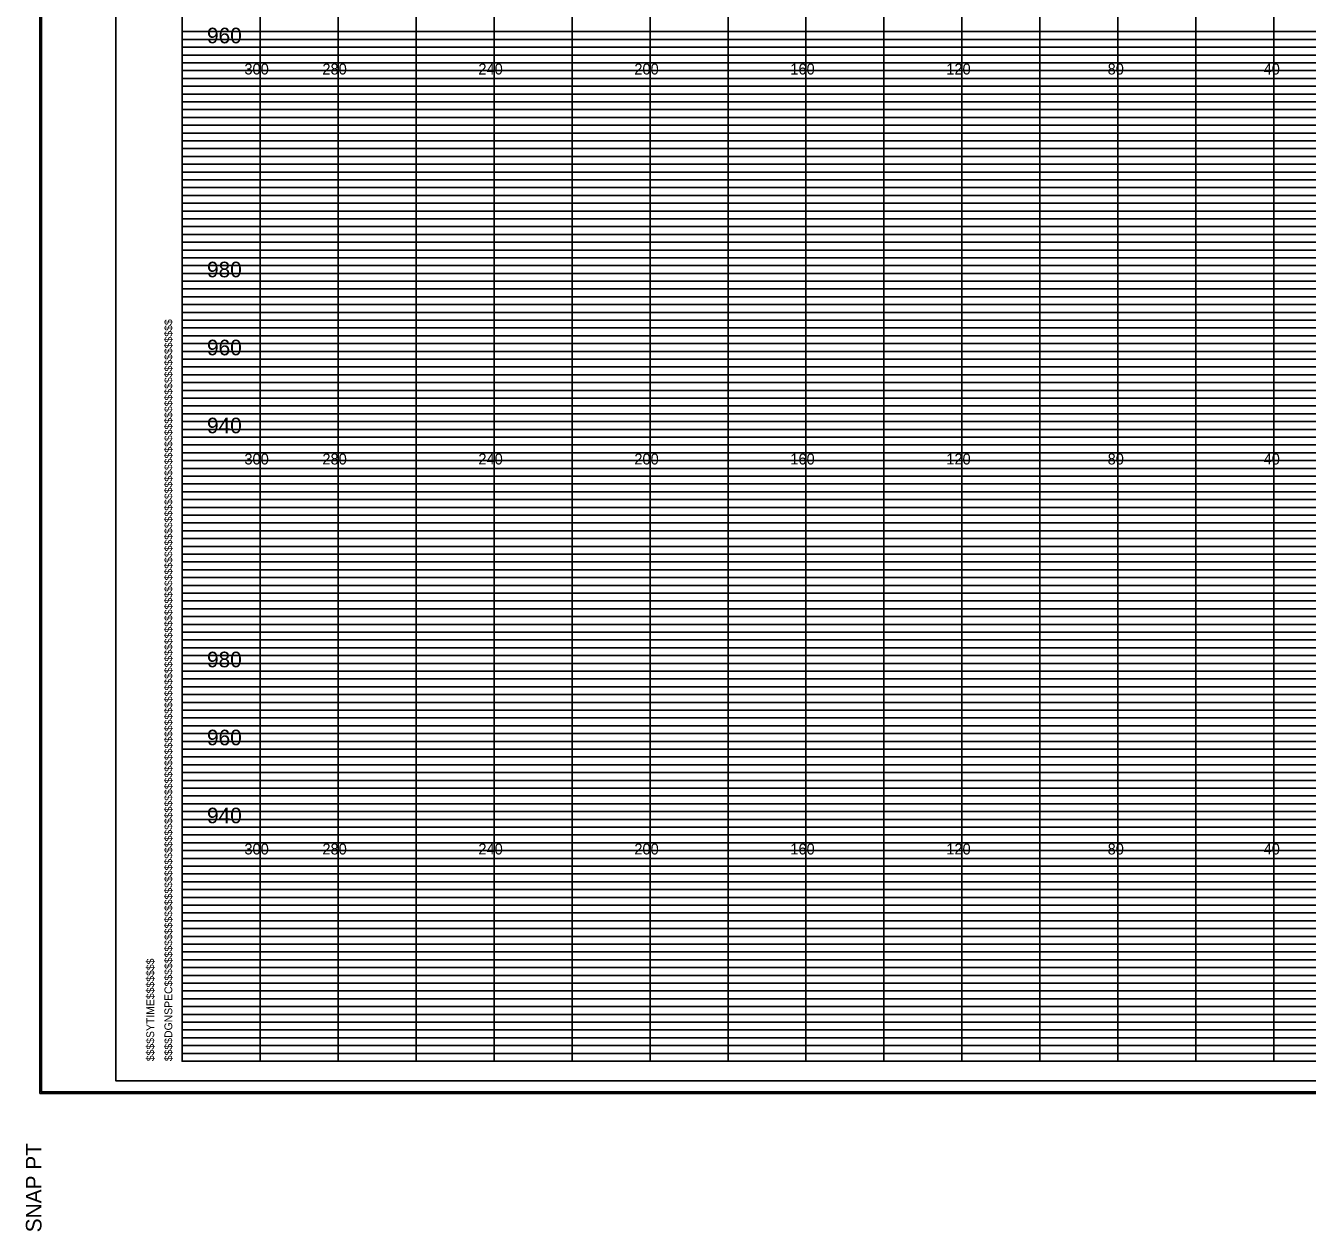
# Model space of a CAD drawing. Extents: x 2313580 to 2322968, y 282099 to 303247.
# Drawn here: x 2320006 to 2320334.7, y 287544 to 287853.2 of the extents above; entities that cross this region are included whole.
import ezdxf

# ---------------------------------------------------------------- set-up
doc = ezdxf.new("R2010")
doc.units = 0
for name, color, linetype in [('DESIGN - SHEET - Corner Text', 7, 'Continuous'), ('DESIGN - SHEET - Light Grid', 7, 'Continuous'), ('DESIGN - SHEET - Linework', 7, 'Continuous'), ('DESIGN - SHEET - Plot Shape', 7, 'Continuous'), ('DESIGN - TYPICAL - Text', 7, 'Continuous')]:
    doc.layers.add(name, color=color, linetype=linetype)

msp = doc.modelspace()

# ---------------------------------------------------------------- linework, layer by layer
at = {"layer": 'DESIGN - SHEET - Light Grid'}
for p, q in [((2320046.08, 287851.67), (2320206.08, 287851.67)), ((2320046.08, 287849.67), (2320206.08, 287849.67)), ((2320206.08, 287851.67), (2320366.08, 287851.67)), ((2320206.08, 287849.67), (2320366.08, 287849.67)), ((2320046.08, 287845.67), (2320206.08, 287845.67)), ((2320206.08, 287845.67), (2320366.08, 287845.67)), ((2320046.08, 287843.67), (2320206.08, 287843.67)), ((2320206.08, 287843.67), (2320366.08, 287843.67)), ((2320046.08, 287841.67), (2320206.08, 287841.67)), ((2320046.08, 287839.67), (2320206.08, 287839.67)), ((2320206.08, 287841.67), (2320366.08, 287841.67)), ((2320206.08, 287839.67), (2320366.08, 287839.67)), ((2320046.08, 287837.67), (2320206.08, 287837.67)), ((2320046.08, 287835.67), (2320206.08, 287835.67)), ((2320206.08, 287837.67), (2320366.08, 287837.67)), ((2320206.08, 287835.67), (2320366.08, 287835.67)), ((2320046.08, 287833.67), (2320206.08, 287833.67)), ((2320206.08, 287833.67), (2320366.08, 287833.67)), ((2320046.08, 287831.67), (2320206.08, 287831.67)), ((2320046.08, 287829.67), (2320206.08, 287829.67)), ((2320206.08, 287831.67), (2320366.08, 287831.67)), ((2320206.08, 287829.67), (2320366.08, 287829.67)), ((2320046.08, 287825.67), (2320206.08, 287825.67)), ((2320206.08, 287825.67), (2320366.08, 287825.67)), ((2320046.08, 287823.67), (2320206.08, 287823.67)), ((2320206.08, 287823.67), (2320366.08, 287823.67)), ((2320046.08, 287821.67), (2320206.08, 287821.67)), ((2320046.08, 287819.67), (2320206.08, 287819.67)), ((2320206.08, 287821.67), (2320366.08, 287821.67)), ((2320206.08, 287819.67), (2320366.08, 287819.67)), ((2320046.08, 287817.67), (2320206.08, 287817.67)), ((2320206.08, 287817.67), (2320366.08, 287817.67)), ((2320046.08, 287815.67), (2320206.08, 287815.67)), ((2320046.08, 287813.67), (2320206.08, 287813.67)), ((2320206.08, 287815.67), (2320366.08, 287815.67)), ((2320206.08, 287813.67), (2320366.08, 287813.67)), ((2320046.08, 287811.67), (2320206.08, 287811.67)), ((2320046.08, 287809.67), (2320206.08, 287809.67)), ((2320206.08, 287811.67), (2320366.08, 287811.67)), ((2320206.08, 287809.67), (2320366.08, 287809.67)), ((2320046.08, 287805.67), (2320206.08, 287805.67)), ((2320046.08, 287803.67), (2320206.08, 287803.67)), ((2320206.08, 287805.67), (2320366.08, 287805.67)), ((2320206.08, 287803.67), (2320366.08, 287803.67)), ((2320046.08, 287801.67), (2320206.08, 287801.67)), ((2320046.08, 287799.67), (2320206.08, 287799.67)), ((2320206.08, 287801.67), (2320366.08, 287801.67)), ((2320206.08, 287799.67), (2320366.08, 287799.67)), ((2320046.08, 287797.67), (2320206.08, 287797.67)), ((2320206.08, 287797.67), (2320366.08, 287797.67)), ((2320046.08, 287795.67), (2320206.08, 287795.67)), ((2320046.08, 287793.67), (2320206.08, 287793.67)), ((2320206.08, 287795.67), (2320366.08, 287795.67)), ((2320206.08, 287793.67), (2320366.08, 287793.67)), ((2320046.08, 287791.67), (2320206.08, 287791.67)), ((2320046.08, 287789.67), (2320206.08, 287789.67)), ((2320206.08, 287791.67), (2320366.08, 287791.67)), ((2320206.08, 287789.67), (2320366.08, 287789.67)), ((2320046.08, 287785.67), (2320206.08, 287785.67)), ((2320046.08, 287783.67), (2320206.08, 287783.67)), ((2320206.08, 287785.67), (2320366.08, 287785.67)), ((2320206.08, 287783.67), (2320366.08, 287783.67)), ((2320046.08, 287781.67), (2320206.08, 287781.67)), ((2320046.08, 287779.67), (2320206.08, 287779.67)), ((2320206.08, 287781.67), (2320366.08, 287781.67)), ((2320206.08, 287779.67), (2320366.08, 287779.67)), ((2320046.08, 287777.67), (2320206.08, 287777.67)), ((2320206.08, 287777.67), (2320366.08, 287777.67)), ((2320046.08, 287775.67), (2320206.08, 287775.67)), ((2320046.08, 287773.67), (2320206.08, 287773.67)), ((2320206.08, 287775.67), (2320366.08, 287775.67)), ((2320206.08, 287773.67), (2320366.08, 287773.67)), ((2320046.08, 287771.67), (2320206.08, 287771.67)), ((2320206.08, 287771.67), (2320366.08, 287771.67)), ((2320046.08, 287769.67), (2320206.08, 287769.67)), ((2320206.08, 287769.67), (2320366.08, 287769.67)), ((2320046.08, 287765.67), (2320206.08, 287765.67)), ((2320046.08, 287763.67), (2320206.08, 287763.67)), ((2320206.08, 287765.67), (2320366.08, 287765.67)), ((2320206.08, 287763.67), (2320366.08, 287763.67)), ((2320046.08, 287761.67), (2320206.08, 287761.67)), ((2320206.08, 287761.67), (2320366.08, 287761.67)), ((2320046.08, 287759.67), (2320206.08, 287759.67)), ((2320046.08, 287757.67), (2320206.08, 287757.67)), ((2320206.08, 287759.67), (2320366.08, 287759.67)), ((2320206.08, 287757.67), (2320366.08, 287757.67)), ((2320046.08, 287755.67), (2320206.08, 287755.67)), ((2320046.08, 287753.67), (2320206.08, 287753.67)), ((2320206.08, 287755.67), (2320366.08, 287755.67)), ((2320206.08, 287753.67), (2320366.08, 287753.67)), ((2320046.08, 287751.67), (2320206.08, 287751.67)), ((2320206.08, 287751.67), (2320366.08, 287751.67)), ((2320046.08, 287749.67), (2320206.08, 287749.67)), ((2320206.08, 287749.67), (2320366.08, 287749.67)), ((2320046.08, 287745.67), (2320206.08, 287745.67)), ((2320046.08, 287743.67), (2320206.08, 287743.67)), ((2320206.08, 287745.67), (2320366.08, 287745.67)), ((2320206.08, 287743.67), (2320366.08, 287743.67)), ((2320046.08, 287741.67), (2320206.08, 287741.67)), ((2320206.08, 287741.67), (2320366.08, 287741.67)), ((2320046.08, 287739.67), (2320206.08, 287739.67)), ((2320046.08, 287737.67), (2320206.08, 287737.67)), ((2320206.08, 287739.67), (2320366.08, 287739.67)), ((2320206.08, 287737.67), (2320366.08, 287737.67)), ((2320046.08, 287735.67), (2320206.08, 287735.67)), ((2320046.08, 287733.67), (2320206.08, 287733.67)), ((2320206.08, 287735.67), (2320366.08, 287735.67)), ((2320206.08, 287733.67), (2320366.08, 287733.67)), ((2320046.08, 287731.67), (2320206.08, 287731.67)), ((2320206.08, 287731.67), (2320366.08, 287731.67)), ((2320046.08, 287729.67), (2320206.08, 287729.67)), ((2320206.08, 287729.67), (2320366.08, 287729.67)), ((2320046.08, 287725.67), (2320206.08, 287725.67)), ((2320206.08, 287725.67), (2320366.08, 287725.67)), ((2320046.08, 287723.67), (2320206.08, 287723.67)), ((2320046.08, 287721.67), (2320206.08, 287721.67)), ((2320206.08, 287723.67), (2320366.08, 287723.67)), ((2320206.08, 287721.67), (2320366.08, 287721.67)), ((2320046.08, 287719.67), (2320206.08, 287719.67)), ((2320046.08, 287717.67), (2320206.08, 287717.67)), ((2320206.08, 287719.67), (2320366.08, 287719.67)), ((2320206.08, 287717.67), (2320366.08, 287717.67)), ((2320046.08, 287715.67), (2320206.08, 287715.67)), ((2320206.08, 287715.67), (2320366.08, 287715.67)), ((2320046.08, 287713.67), (2320206.08, 287713.67)), ((2320046.08, 287711.67), (2320206.08, 287711.67)), ((2320206.08, 287713.67), (2320366.08, 287713.67)), ((2320206.08, 287711.67), (2320366.08, 287711.67)), ((2320046.08, 287709.67), (2320206.08, 287709.67)), ((2320206.08, 287709.67), (2320366.08, 287709.67)), ((2320046.08, 287705.67), (2320206.08, 287705.67)), ((2320206.08, 287705.67), (2320366.08, 287705.67)), ((2320046.08, 287703.67), (2320206.08, 287703.67)), ((2320046.08, 287701.67), (2320206.08, 287701.67)), ((2320206.08, 287703.67), (2320366.08, 287703.67)), ((2320206.08, 287701.67), (2320366.08, 287701.67)), ((2320046.08, 287699.67), (2320206.08, 287699.67)), ((2320046.08, 287697.67), (2320206.08, 287697.67)), ((2320206.08, 287699.67), (2320366.08, 287699.67)), ((2320206.08, 287697.67), (2320366.08, 287697.67)), ((2320046.08, 287695.67), (2320206.08, 287695.67)), ((2320206.08, 287695.67), (2320366.08, 287695.67)), ((2320046.08, 287693.67), (2320206.08, 287693.67)), ((2320046.08, 287691.67), (2320206.08, 287691.67)), ((2320206.08, 287693.67), (2320366.08, 287693.67)), ((2320206.08, 287691.67), (2320366.08, 287691.67)), ((2320046.08, 287689.67), (2320206.08, 287689.67)), ((2320206.08, 287689.67), (2320366.08, 287689.67)), ((2320046.08, 287685.67), (2320206.08, 287685.67)), ((2320206.08, 287685.67), (2320366.08, 287685.67)), ((2320046.08, 287683.67), (2320206.08, 287683.67)), ((2320046.08, 287681.67), (2320206.08, 287681.67)), ((2320206.08, 287683.67), (2320366.08, 287683.67)), ((2320206.08, 287681.67), (2320366.08, 287681.67)), ((2320046.08, 287679.67), (2320206.08, 287679.67)), ((2320046.08, 287677.67), (2320206.08, 287677.67)), ((2320206.08, 287679.67), (2320366.08, 287679.67)), ((2320206.08, 287677.67), (2320366.08, 287677.67)), ((2320046.08, 287675.67), (2320206.08, 287675.67)), ((2320206.08, 287675.67), (2320366.08, 287675.67)), ((2320046.08, 287673.67), (2320206.08, 287673.67)), ((2320046.08, 287671.67), (2320206.08, 287671.67)), ((2320206.08, 287673.67), (2320366.08, 287673.67)), ((2320206.08, 287671.67), (2320366.08, 287671.67)), ((2320046.08, 287669.67), (2320206.08, 287669.67)), ((2320206.08, 287669.67), (2320366.08, 287669.67)), ((2320046.08, 287665.67), (2320206.08, 287665.67)), ((2320206.08, 287665.67), (2320366.08, 287665.67)), ((2320046.08, 287663.67), (2320206.08, 287663.67)), ((2320046.08, 287661.67), (2320206.08, 287661.67)), ((2320206.08, 287663.67), (2320366.08, 287663.67)), ((2320206.08, 287661.67), (2320366.08, 287661.67)), ((2320046.08, 287659.67), (2320206.08, 287659.67)), ((2320206.08, 287659.67), (2320366.08, 287659.67)), ((2320046.08, 287657.67), (2320206.08, 287657.67)), ((2320046.08, 287655.67), (2320206.08, 287655.67)), ((2320206.08, 287657.67), (2320366.08, 287657.67)), ((2320206.08, 287655.67), (2320366.08, 287655.67)), ((2320046.08, 287653.67), (2320206.08, 287653.67)), ((2320046.08, 287651.67), (2320206.08, 287651.67)), ((2320206.08, 287653.67), (2320366.08, 287653.67)), ((2320206.08, 287651.67), (2320366.08, 287651.67)), ((2320046.08, 287649.67), (2320206.08, 287649.67)), ((2320206.08, 287649.67), (2320366.08, 287649.67)), ((2320046.08, 287645.67), (2320206.08, 287645.67)), ((2320206.08, 287645.67), (2320366.08, 287645.67)), ((2320046.08, 287643.67), (2320206.08, 287643.67)), ((2320046.08, 287641.67), (2320206.08, 287641.67)), ((2320206.08, 287643.67), (2320366.08, 287643.67)), ((2320206.08, 287641.67), (2320366.08, 287641.67)), ((2320046.08, 287639.67), (2320206.08, 287639.67)), ((2320206.08, 287639.67), (2320366.08, 287639.67)), ((2320046.08, 287637.67), (2320206.08, 287637.67)), ((2320046.08, 287635.67), (2320206.08, 287635.67)), ((2320206.08, 287637.67), (2320366.08, 287637.67)), ((2320206.08, 287635.67), (2320366.08, 287635.67)), ((2320046.08, 287633.67), (2320206.08, 287633.67)), ((2320046.08, 287631.67), (2320206.08, 287631.67)), ((2320206.08, 287633.67), (2320366.08, 287633.67)), ((2320206.08, 287631.67), (2320366.08, 287631.67)), ((2320046.08, 287629.67), (2320206.08, 287629.67)), ((2320206.08, 287629.67), (2320366.08, 287629.67)), ((2320046.08, 287625.67), (2320206.08, 287625.67)), ((2320206.08, 287625.67), (2320366.08, 287625.67)), ((2320046.08, 287623.67), (2320206.08, 287623.67)), ((2320206.08, 287623.67), (2320366.08, 287623.67)), ((2320046.08, 287621.67), (2320206.08, 287621.67)), ((2320046.08, 287619.67), (2320206.08, 287619.67)), ((2320206.08, 287621.67), (2320366.08, 287621.67)), ((2320206.08, 287619.67), (2320366.08, 287619.67)), ((2320046.08, 287617.67), (2320206.08, 287617.67)), ((2320046.08, 287615.67), (2320206.08, 287615.67)), ((2320206.08, 287617.67), (2320366.08, 287617.67)), ((2320206.08, 287615.67), (2320366.08, 287615.67)), ((2320046.08, 287613.67), (2320206.08, 287613.67)), ((2320206.08, 287613.67), (2320366.08, 287613.67)), ((2320046.08, 287611.67), (2320206.08, 287611.67)), ((2320046.08, 287609.67), (2320206.08, 287609.67)), ((2320206.08, 287611.67), (2320366.08, 287611.67)), ((2320206.08, 287609.67), (2320366.08, 287609.67)), ((2320046.08, 287605.67), (2320206.08, 287605.67)), ((2320206.08, 287605.67), (2320366.08, 287605.67)), ((2320046.08, 287603.67), (2320206.08, 287603.67)), ((2320206.08, 287603.67), (2320366.08, 287603.67)), ((2320046.08, 287601.67), (2320206.08, 287601.67)), ((2320046.08, 287599.67), (2320206.08, 287599.67)), ((2320206.08, 287601.67), (2320366.08, 287601.67)), ((2320206.08, 287599.67), (2320366.08, 287599.67)), ((2320046.08, 287597.67), (2320206.08, 287597.67)), ((2320046.08, 287595.67), (2320206.08, 287595.67)), ((2320206.08, 287597.67), (2320366.08, 287597.67)), ((2320206.08, 287595.67), (2320366.08, 287595.67)), ((2320046.08, 287593.67), (2320206.08, 287593.67)), ((2320206.08, 287593.67), (2320366.08, 287593.67)), ((2320046.08, 287591.67), (2320206.08, 287591.67)), ((2320046.08, 287589.67), (2320206.08, 287589.67)), ((2320206.08, 287591.67), (2320366.08, 287591.67)), ((2320206.08, 287589.67), (2320366.08, 287589.67))]:
    msp.add_line(p, q, dxfattribs=at)
at = {"layer": 'DESIGN - SHEET - Linework'}
for p, q in [((2320009.62, 287579.39), (2320009.62, 288015.95)), ((2320066.08, 287587.67), (2320066.08, 288007.67)), ((2320086.08, 287587.67), (2320086.08, 288007.67)), ((2320106.08, 287587.67), (2320106.08, 288007.67)), ((2320126.08, 287587.67), (2320126.08, 288007.67)), ((2320146.08, 287587.67), (2320146.08, 288007.67)), ((2320166.08, 287587.67), (2320166.08, 288007.67)), ((2320186.08, 287587.67), (2320186.08, 288007.67)), ((2320206.08, 287587.67), (2320206.08, 288007.67)), ((2320226.08, 287587.67), (2320226.08, 288007.67)), ((2320246.08, 287587.67), (2320246.08, 288007.67)), ((2320266.08, 287587.67), (2320266.08, 288007.67)), ((2320286.08, 287587.67), (2320286.08, 288007.67)), ((2320306.08, 287587.67), (2320306.08, 288007.67)), ((2320326.08, 287587.67), (2320326.08, 288007.67)), ((2320046.08, 287847.67), (2320686.08, 287847.67)), ((2320046.08, 287827.67), (2320686.08, 287827.67)), ((2320046.08, 287807.67), (2320686.08, 287807.67)), ((2320046.08, 287787.67), (2320686.08, 287787.67)), ((2320046.08, 287767.67), (2320686.08, 287767.67)), ((2320046.08, 287747.67), (2320686.08, 287747.67)), ((2320046.08, 287727.67), (2320686.08, 287727.67)), ((2320046.08, 287707.67), (2320686.08, 287707.67)), ((2320046.08, 287687.67), (2320686.08, 287687.67)), ((2320046.08, 287667.67), (2320686.08, 287667.67)), ((2320046.08, 287647.67), (2320686.08, 287647.67)), ((2320046.08, 287627.67), (2320686.08, 287627.67)), ((2320046.08, 287607.67), (2320686.08, 287607.67)), ((2320009.62, 287579.39), (2320690.42, 287579.39))]:
    msp.add_line(p, q, dxfattribs=at)
msp.add_lwpolyline([(2320046.08, 288007.67), (2320046.08, 287587.67), (2320686.08, 287587.67), (2320686.08, 288007.67), (2320046.08, 288007.67)], dxfattribs=at)
at = {"layer": 'DESIGN - SHEET - Plot Shape'}
for points in [[(2320010.02, 288015.55), (2320690.02, 288015.55), (2320690.02, 287579.79), (2320010.02, 287579.79)], [(2320029.08, 288007.67), (2320686.08, 288007.67), (2320686.08, 287582.67), (2320029.08, 287582.67)]]:
    msp.add_lwpolyline(points, close=True, dxfattribs=at)

# ---------------------------------------------------------------- texts
at = {"layer": 'DESIGN - SHEET - Corner Text'}
for s, height, p in [('$$$$DGNSPEC$$$$$$$$$$$$$$$$$$$$$$$$$$$$$$$$$$$$$$$$$$$$$$$$$$$$$$$$$$$$$$$$$$$$$$$$$$$$$$$$$$$$$$$$$$$$$$$$$$$$$$$$$$$$$$$$$$$', 2.00004, (2320043.56, 287587.67)), ('$$$$SYTIME$$$$$$$', 2, (2320038.92, 287587.67)), ('SNAP PT  ', 4, (2320010.02, 287543.79))]:
    msp.add_text(s, height=height, rotation=90, dxfattribs=at).set_placement(p)
at = {"layer": 'DESIGN - SHEET - Linework'}
for p in [(2320066.08, 287847.67), (2320066.08, 287747.67), (2320066.08, 287647.67)]:
    msp.add_text('-', height=0.0001, dxfattribs=at).set_placement(p)
at = {"layer": 'DESIGN - TYPICAL - Text'}
for s, height, p in [('960', 4, (2320052.46, 287848.67)), ('-300', 2.8, (2320060.82, 287840.67)), ('-280', 2.8, (2320080.82, 287840.67)), ('-240', 2.8, (2320120.82, 287840.67)), ('-200', 2.8, (2320160.82, 287840.67)), ('-160', 2.8, (2320200.82, 287840.67)), ('-120', 2.8, (2320240.82, 287840.67)), ('-80', 2.8, (2320282.19, 287840.67)), ('-40', 2.8, (2320322.19, 287840.67)), ('980', 4, (2320052.46, 287788.67)), ('960', 4, (2320052.46, 287768.67)), ('940', 4, (2320052.46, 287748.67)), ('-300', 2.8, (2320060.82, 287740.67)), ('-280', 2.8, (2320080.82, 287740.67)), ('-240', 2.8, (2320120.82, 287740.67)), ('-200', 2.8, (2320160.82, 287740.67)), ('-160', 2.8, (2320200.82, 287740.67)), ('-120', 2.8, (2320240.82, 287740.67)), ('-80', 2.8, (2320282.19, 287740.67)), ('-40', 2.8, (2320322.19, 287740.67)), ('980', 4, (2320052.46, 287688.67)), ('960', 4, (2320052.46, 287668.67)), ('940', 4, (2320052.46, 287648.67)), ('-300', 2.8, (2320060.82, 287640.67)), ('-280', 2.8, (2320080.82, 287640.67)), ('-240', 2.8, (2320120.82, 287640.67)), ('-200', 2.8, (2320160.82, 287640.67)), ('-160', 2.8, (2320200.82, 287640.67)), ('-120', 2.8, (2320240.82, 287640.67)), ('-80', 2.8, (2320282.19, 287640.67)), ('-40', 2.8, (2320322.19, 287640.67))]:
    msp.add_text(s, height=height, dxfattribs=at).set_placement(p)

doc.saveas('drawing.dxf')
